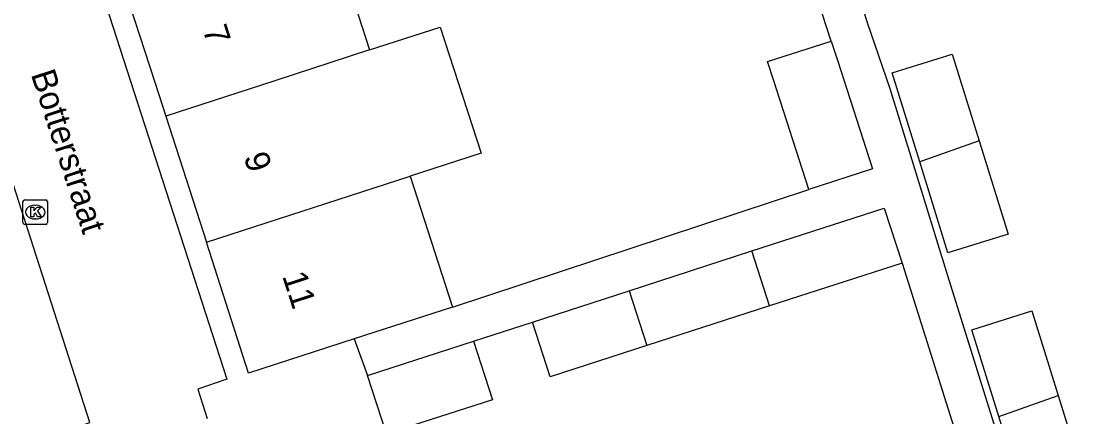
# Model space of a CAD drawing. Extents: x 159377 to 159983, y 382996 to 383595.
# Drawn here: x 159661.06 to 159704.59, y 383236.31 to 383252.43 of the extents above; entities that cross this region are included whole.
import ezdxf

# ---------------------------------------------------------------- set-up
doc = ezdxf.new("R2010")
doc.units = 0
for name, color, linetype in [('IMGEO_Kolk', 7, 'Continuous'), ('IMGEO_Openbare_ruimte_label', 7, 'Continuous'), ('IMGEO_Pand', 7, 'Continuous'), ('IMGEO_Pand_nummerreeks', 7, 'Continuous'), ('IMGEO_Rijbaan_lokaal_open', 7, 'Continuous'), ('IMGEO_Voetpad_open', 7, 'Continuous')]:
    doc.layers.add(name, color=color, linetype=linetype)

msp = doc.modelspace()

# ---------------------------------------------------------------- linework, layer by layer
at = {"layer": 'IMGEO_Kolk'}
for p, q in [((159661.128, 383244.229), (159661.128, 383245.081)), ((159661.203, 383245.155), (159662.055, 383245.155)), ((159662.129, 383245.081), (159662.129, 383244.229)), ((159661.616, 383244.935), (159661.641, 383244.935)), ((159662.055, 383244.155), (159661.203, 383244.155)), ((159661.639, 383244.375), (159661.614, 383244.375))]:
    msp.add_line(p, q, dxfattribs=at)
for points in [[(159661.128, 383244.229), (159661.128, 383245.081)], [(159661.203, 383245.155), (159662.055, 383245.155)], [(159662.129, 383245.081), (159662.129, 383244.229)], [(159661.449, 383244.855), (159661.572, 383244.855), (159661.572, 383244.704), (159661.702, 383244.855), (159661.866, 383244.855), (159661.72, 383244.704), (159661.873, 383244.455), (159661.721, 383244.455), (159661.636, 383244.619), (159661.572, 383244.552), (159661.572, 383244.455), (159661.449, 383244.455), (159661.449, 383244.855)], [(159662.055, 383244.155), (159661.203, 383244.155)]]:
    msp.add_lwpolyline(points, dxfattribs=at)
for centre, start, end in [((159661.205, 383245.079), 91.552, 178.448), ((159661.205, 383245.079), 91.552, 178.448), ((159662.053, 383245.079), 1.552, 88.448), ((159662.053, 383245.079), 1.552, 88.448), ((159661.205, 383244.231), 181.552, 268.448), ((159661.205, 383244.231), 181.552, 268.448), ((159662.053, 383244.231), 271.552, 358.448), ((159662.053, 383244.231), 271.552, 358.448)]:
    msp.add_arc(centre, 0.0765, start, end, dxfattribs=at)
for centre, major_axis, ratio, start_param, end_param in [((159661.615, 383244.655), (-0.387, 0.002), 0.722429, 4.712389, 7.853982), ((159661.64, 383244.655), (-0.39, 0.002), 0.717154, 1.570796, 4.712389)]:
    msp.add_ellipse(centre, major_axis=major_axis, ratio=ratio, start_param=start_param, end_param=end_param, dxfattribs=at)
at = {"layer": 'IMGEO_Pand'}
for points in [[(159673.612, 383256.411), (159675.276, 383251.267)], [(159665.288, 383253.713), (159666.494, 383250), (159666.955, 383248.57)], [(159675.276, 383251.267), (159678.166, 383252.203), (159679.832, 383247.063), (159676.935, 383246.124)], [(159693.217, 383245.576), (159691.785, 383250.004), (159691.527, 383250.801), (159694.128, 383251.623)], [(159694.128, 383251.623), (159694.38, 383250.844), (159695.812, 383246.415), (159693.217, 383245.576)], [(159675.276, 383251.267), (159671.366, 383250), (159666.955, 383248.57)], [(159697.74, 383246.706), (159696.612, 383250.34), (159699.067, 383251.102), (159700.165, 383247.567)], [(159666.955, 383248.57), (159668.615, 383243.427)], [(159700.165, 383247.567), (159701.347, 383243.758), (159698.891, 383242.996), (159697.74, 383246.706)], [(159700.165, 383247.567), (159697.74, 383246.706)], [(159668.615, 383243.427), (159676.935, 383246.124)], [(159676.935, 383246.124), (159678.66, 383240.777)], [(159690.881, 383243.068), (159696.286, 383244.815), (159697.021, 383242.578)], [(159674.65, 383239.483), (159670.336, 383238.091), (159668.615, 383243.427)], [(159685.873, 383241.448), (159690.881, 383243.068)], [(159691.602, 383240.826), (159690.881, 383243.068)], [(159697.021, 383242.578), (159691.602, 383240.826)], [(159681.925, 383240.172), (159685.873, 383241.448)], [(159685.873, 383241.448), (159686.595, 383239.208)], [(159678.66, 383240.777), (159674.65, 383239.483)], [(159691.602, 383240.826), (159686.595, 383239.208)], [(159700.963, 383236.318), (159699.864, 383239.859), (159702.32, 383240.621), (159703.388, 383237.179)], [(159686.595, 383239.208), (159682.646, 383237.931), (159681.925, 383240.172)], [(159675.194, 383237.996), (159679.518, 383239.394)], [(159679.518, 383239.394), (159680.291, 383237.004), (159675.967, 383235.606)], [(159675.967, 383235.606), (159675.194, 383237.996)], [(159703.388, 383237.179), (159704.594, 383233.291), (159702.139, 383232.53), (159700.963, 383236.318)], [(159700.963, 383236.318), (159703.388, 383237.179)]]:
    msp.add_lwpolyline(points, dxfattribs=at)
at = {"layer": 'IMGEO_Rijbaan_lokaal_open'}
for points in [[(159652.017, 383288.429), (159652.205, 383287.893), (159657.725, 383271.809), (159658.393, 383272.015), (159665.513, 383250), (159669.446, 383237.835), (159668.26, 383237.434), (159668.65, 383236.234)], [(159663.772, 383234.65), (159663.364, 383235.901), (159663.852, 383236.075), (159659.36, 383250), (159653.786, 383267.274), (159654.055, 383267.387), (159647.551, 383286.019), (159647.315, 383286.718)]]:
    msp.add_lwpolyline(points, dxfattribs=at)
at = {"layer": 'IMGEO_Voetpad_open'}
for points in [[(159694.128, 383251.623), (159693.572, 383253.305)], [(159695.365, 383253.117), (159695.59, 383252.391), (159696.512, 383249.693), (159697.469, 383246.61), (159698.877, 383242.072), (159702.568, 383230.227), (159703.816, 383226.296)], [(159678.66, 383240.777), (159693.217, 383245.576)], [(159697.021, 383242.578), (159699.678, 383234.162)], [(159679.518, 383239.394), (159681.925, 383240.172)], [(159674.65, 383239.483), (159675.194, 383237.996)]]:
    msp.add_lwpolyline(points, dxfattribs=at)

# ---------------------------------------------------------------- texts
at = {"layer": 'IMGEO_Openbare_ruimte_label'}
msp.add_text('Botterstraat', height=1, rotation=288.0546, dxfattribs=at).set_placement((159661.442, 383250.278))
at = {"layer": 'IMGEO_Pand_nummerreeks'}
for s, rotation, p in [('7', 287.9151, (159668.453, 383252.104)), ('9', 287.9162, (159670.132, 383246.914)), ('11', 287.9151, (159671.704, 383242.052))]:
    msp.add_text(s, height=1, rotation=rotation, dxfattribs=at).set_placement(p)

doc.saveas('drawing.dxf')
